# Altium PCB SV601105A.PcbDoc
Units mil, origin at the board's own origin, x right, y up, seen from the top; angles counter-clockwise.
Board outline 2000 x 2250 mil, 4 copper layers (Top Layer, GND_PLANE, POWER_PLANE, Bottom Layer), stack 90 mil thick; 33 components, 23 nets, 133 pads, 3 vias.
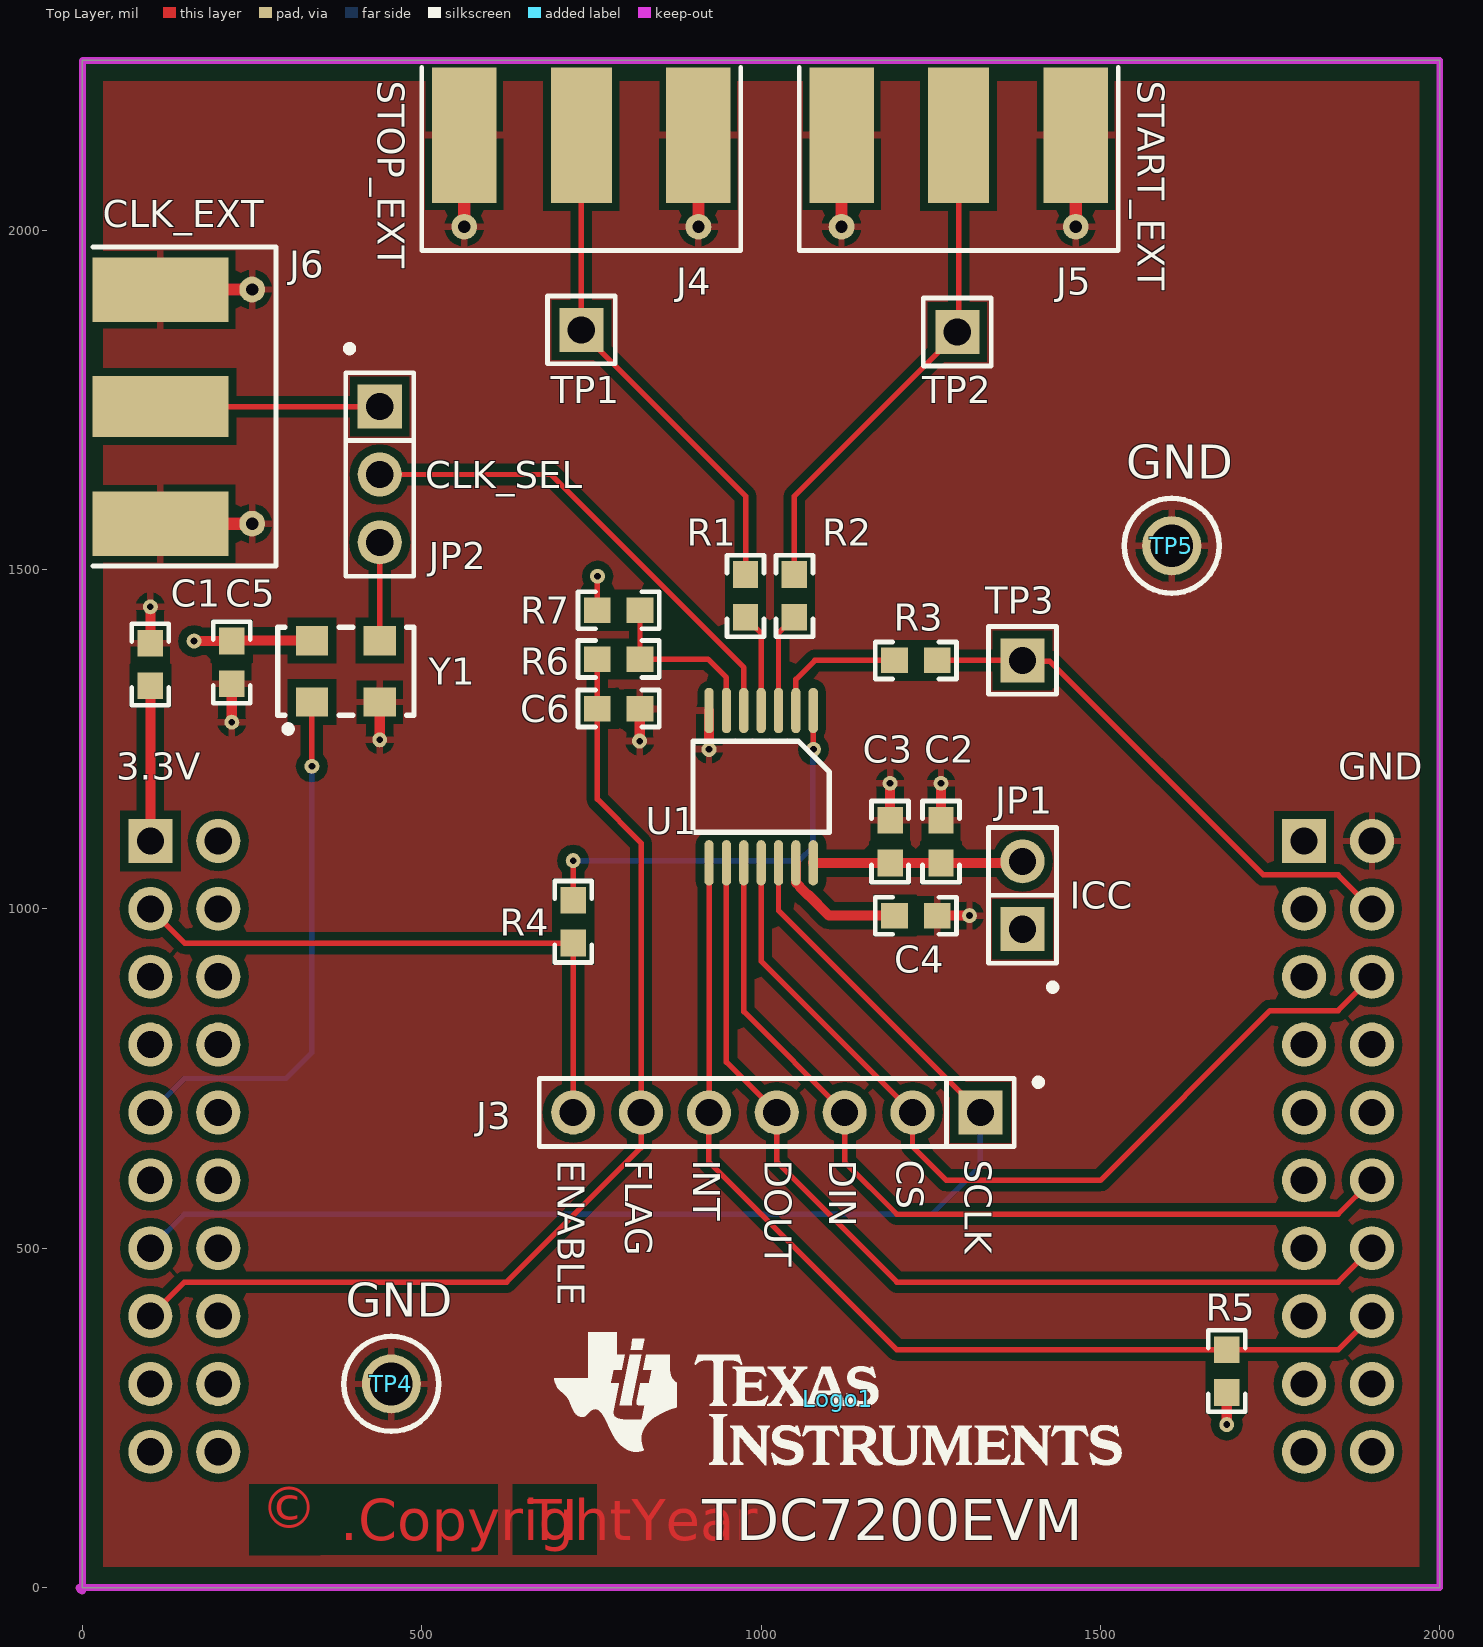
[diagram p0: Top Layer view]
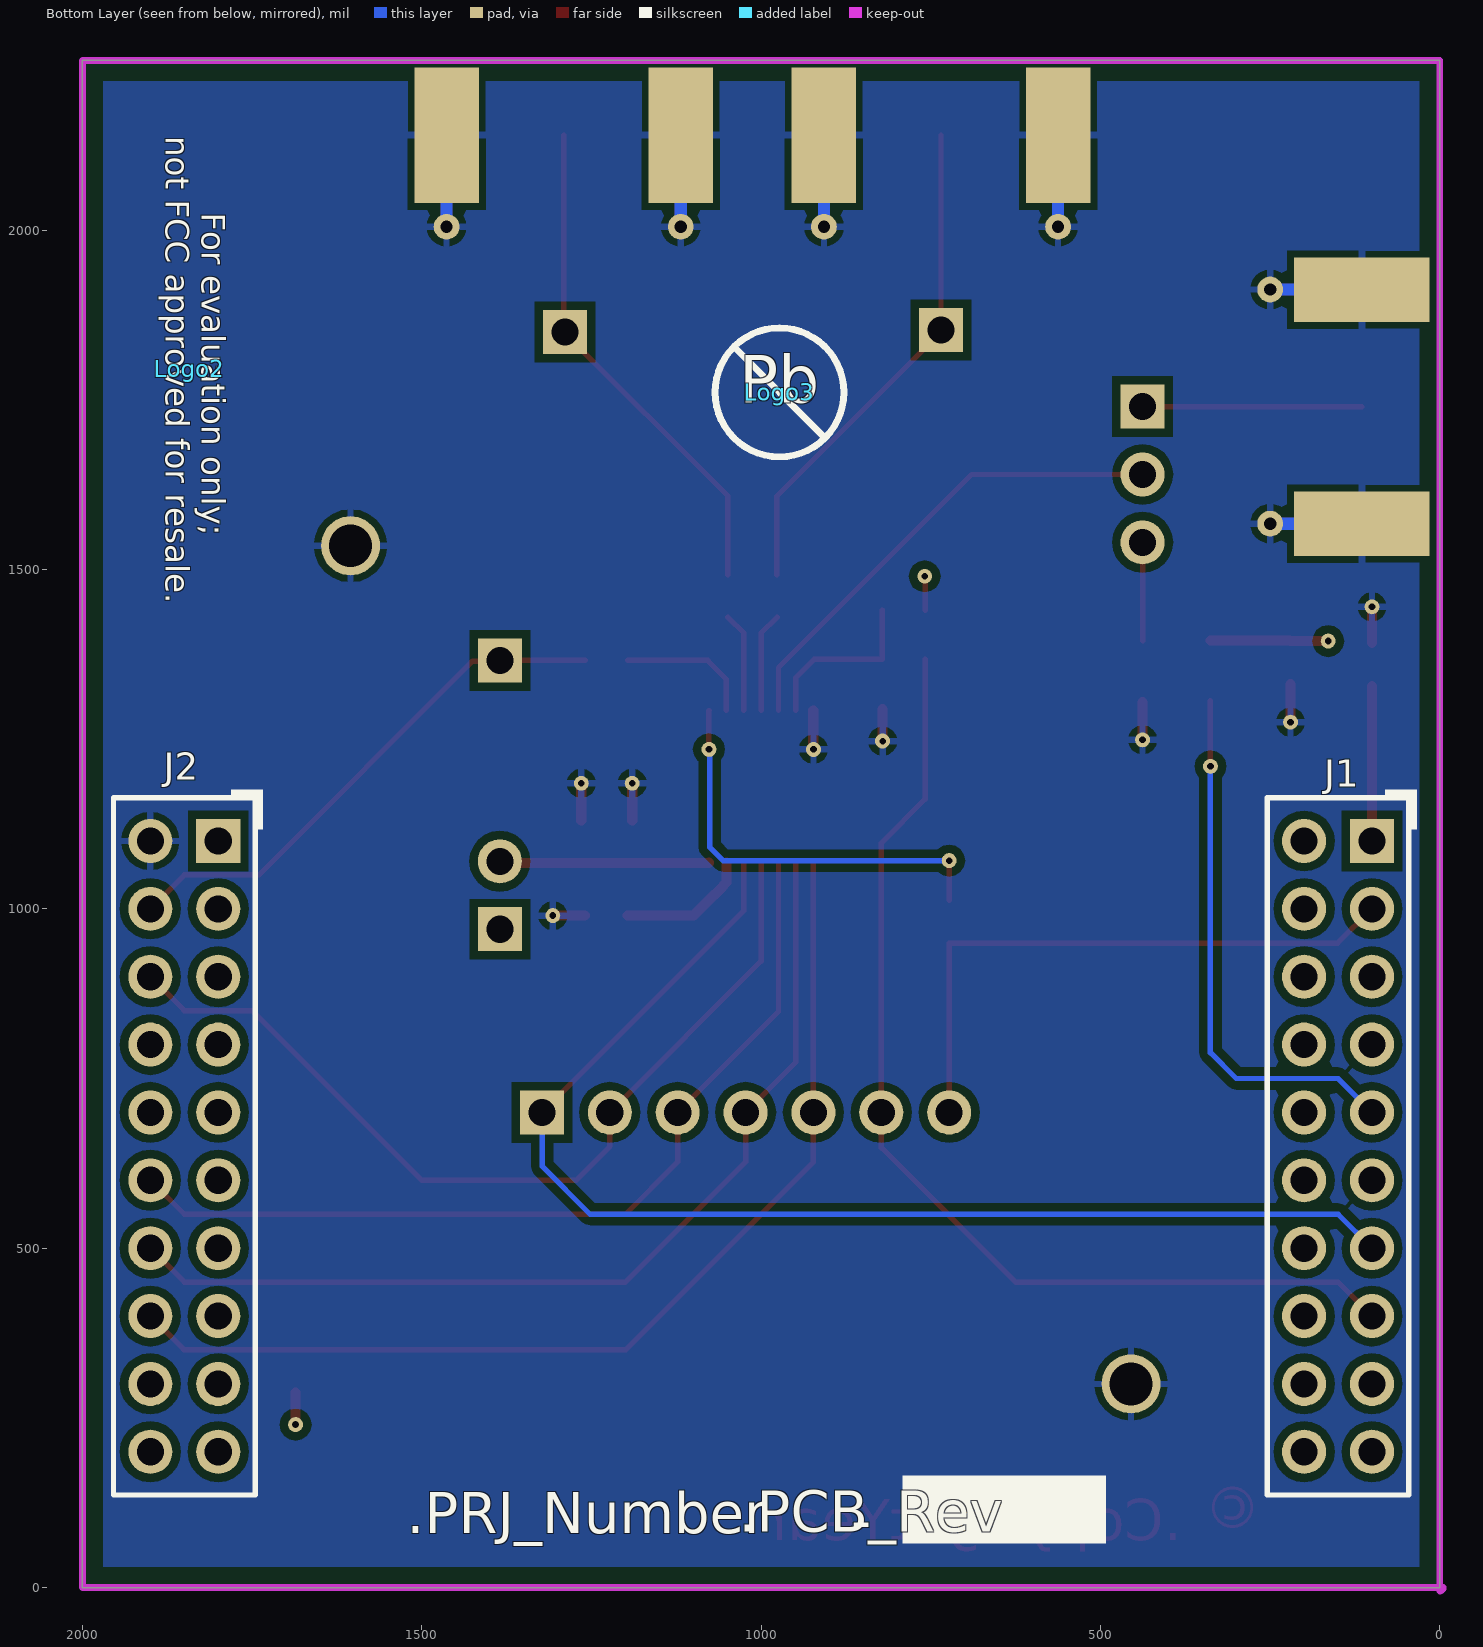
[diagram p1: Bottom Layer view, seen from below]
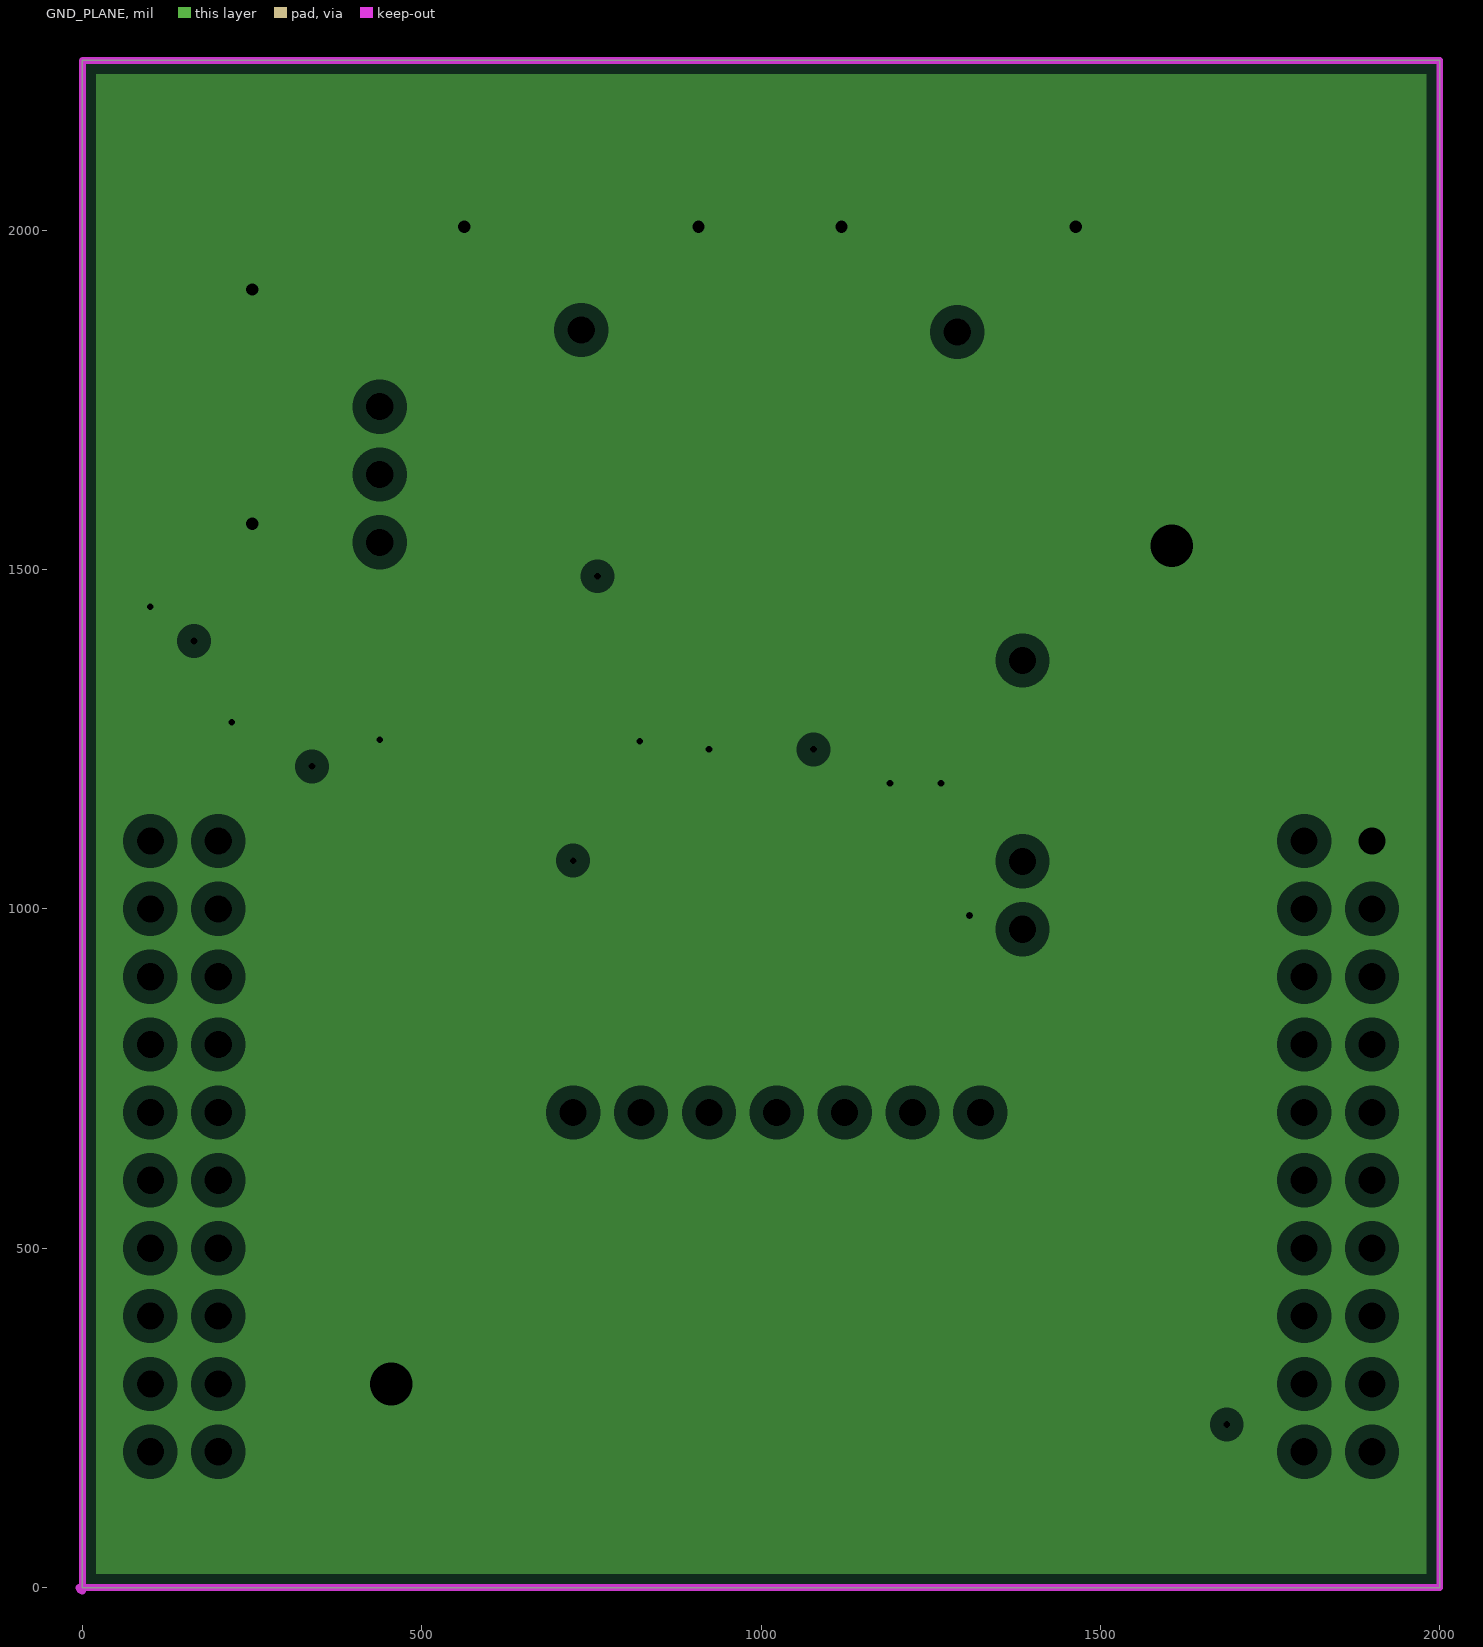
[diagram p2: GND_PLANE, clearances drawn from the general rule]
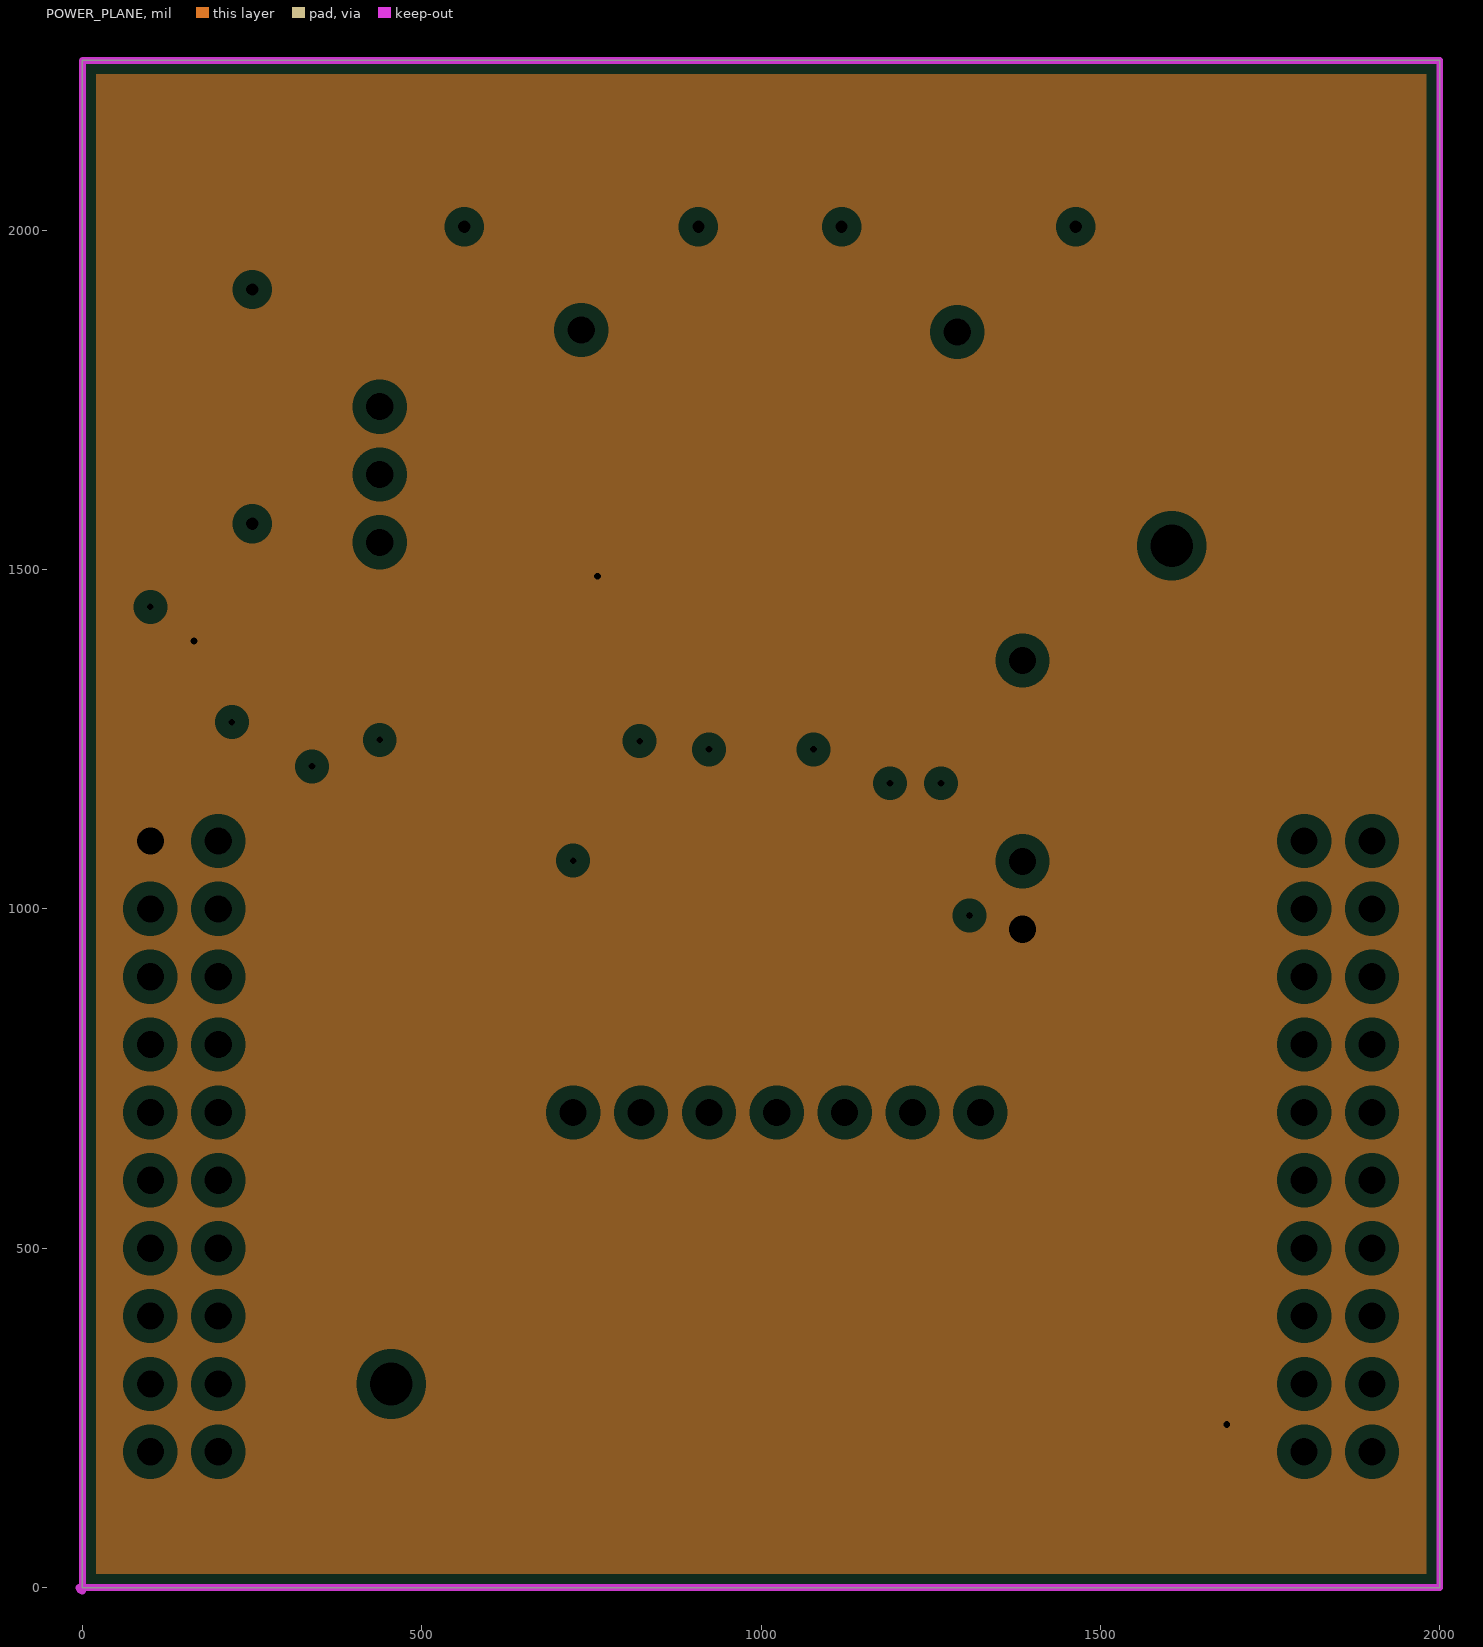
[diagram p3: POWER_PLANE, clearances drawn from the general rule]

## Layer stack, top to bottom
Top Layer: signal copper 1.4
Dielectric: core 59.2, FR-4, Dk 4.8
GND_PLANE: plane copper 1.4, net GND
Dielectric: prepreg 12.6, FR-4, Dk 4.8
POWER_PLANE: plane copper 1.4, net VCC
Dielectric: core 12.6, FR-4, Dk 4.8
Bottom Layer: signal copper 1.4

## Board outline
0,0 0,2250 2000,2250 2000,0

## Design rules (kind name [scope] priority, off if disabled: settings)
AcuteAngle [All] p1: minimum=4.50000000000000E+0001 checktracksonly=FALSE
AssemblyTestPointUsage [All] p1: valid=2
Clearance Clearance_BoardEdge_MountingHoles [OnCopper and InComponentClass('Mounting Holes') vs IsKeepOut] p1: gap=40
Clearance Clearance_BoardEdge_Poly [OnCopper and InPoly vs IsKeepOut] p2: gap=25
Clearance Clearance_BoardEdge [OnCopper and Not InComponentClass('Logo') and not InComponentClass('FiducialMark') and not InRegion(1000,500,4000,800) and Not IsKeepout vs IsKeepOut] p3: gap=5
Clearance Clearance_Poly [InPolygon] p4: gap=12
Clearance [All] p5: gap=6
ComponentClearance ComponentClearance_Logo [InComponentClass('Logo')] p1: gap=50 collisioncheckmode=3 verticalgap=10 showdistances=FALSE
ComponentClearance ComponentClearance_ScrewToNut [(HasFootprint('NY PMS 440 0025 PH')) vs (HasFootprint('Keystone_1902C'))] p2: gap=5 collisioncheckmode=3 verticalgap=10 showdistances=FALSE
ComponentClearance ComponentClearance_MountingHoles [InComponentClass('Mounting Holes')] p3: gap=250 collisioncheckmode=3 verticalgap=100000 showdistances=FALSE
ComponentClearance ComponentClearance_SmallPassives [HasFootprint('0201*') or HasFootprint('0402*') or HasFootprint('0508') or HasFootprint('0603*') or HasFootprint('0612') or HasFootprint('0805*') or HasFootprint('0815*') or HasFootprint('0830*') or HasFootprint('1206*') or HasFootprint('1210*') or HasFootprint('1808*') or HasFootprint('1812*') or HasFootprint('1825*') or HasFootprint('2010*') or HasFootprint('2220*') or HasFootprint('2225*') or HasFootprint('2512*') or HasFootprint('2728*') or HasFootprint('3518*') vs HasFootprint('0201*') or HasFootprint('0402*') or HasFootprint('0508') or HasFootprint('0603*') or HasFootprint('0612') or HasFootprint('0805*') or HasFootprint('0815*') or HasFootprint('0830*') or HasFootprint('1206*') or HasFootprint('1210*') or HasFootprint('1808*') or HasFootprint('1812*') or HasFootprint('1825*') or HasFootprint('2010*') or HasFootprint('2220*') or HasFootprint('2225*') or HasFootprint('2512*') or HasFootprint('2728*') or HasFootprint('3518*')] p4: gap=20 collisioncheckmode=3 verticalgap=10 showdistances=FALSE
ComponentClearance ComponentClearance_THtoSMT [IsThruComponent vs IsSMTComponent] p5: gap=20 collisioncheckmode=3 verticalgap=30 showdistances=FALSE
ComponentClearance ComponentClearance_THtoTH [IsThruComponent vs IsThruComponent] p6: gap=20 collisioncheckmode=3 verticalgap=30 showdistances=FALSE
ComponentClearance [All] p7: gap=40 collisioncheckmode=3 verticalgap=10 showdistances=FALSE
DiffPairsRouting [All] p1: maxlimit=100 minlimit=10 mostfreqgap=10 maxuncoupledlength=1000
FabricationTestPointUsage TestPointUsage [All] p1: valid=2 allowmultiple=FALSE
FabricationTestpoint Testpoint [All] p1: side=3 testpointundercomponent=TRUE minsize=40 maxsize=100 preferedsize=60 minholesize=0 maxholesize=40 preferedholesize=32 testpointgrid=1 allowsidetop=TRUE allowsidebottom=TRUE usegrid=TRUE gridtolerance=0.01
FanoutControl Fanout_LCC [IsLCC] p1: bgadir=Out bgaviamode=Centered fanoutstyle=Auto fanoutdirection=Alternating viagrid=1 // Fanout_LCC (Default Rule)
FanoutControl Fanout_BGA [IsBGA] p2: bgadir=Out bgaviamode=Centered fanoutstyle=Auto fanoutdirection=Alternating viagrid=1 // Fanout_BGA (Default Rule)
FanoutControl Fanout_Default [All] p4: bgadir=Out bgaviamode=Centered fanoutstyle=Auto fanoutdirection=Alternating viagrid=1 // Fanout_Default (Default Rule)
FanoutControl Fanout_Small [(CompPinCount < 5)] p5: bgadir=Out bgaviamode=Centered fanoutstyle=Auto fanoutdirection=OutThenIn viagrid=1 // Fanout_Small (Default Rule)
HoleSize [All] p1: absolutevalues=TRUE maxlimit=251 minlimit=8 maxpercent=80.000 minpercent=20.000
MinimumAnnularRing [All] p1: minimumring=5
MinimumSolderMaskSliver MinimumSolderMaskSliver_Logo [InComponentClass('Logo') vs InComponentClass('Logo')] p1: minsoldermaskwidth=0.7
MinimumSolderMaskSliver [All] p2: minsoldermaskwidth=4
PlaneClearance [All] p1: clearance=20
PlaneConnect [All] p1: planeconnectstyle=Relief reliefexpansion=10 reliefentries=4 reliefconductorwidth=10 reliefairgap=10
PolygonConnect [All] p1: connectstyle=Relief reliefconductorwidth=10 reliefentries=4 polygonreliefangle="90 Angle" airgapwidth=10
RoutingVias [All] p1: holewidth=16 width=34 viastyle="Through Hole" minholewidth=8 minwidth=20 maxholewidth=40 maxwidth=65
SMDToCorner [All] p1: distance=16000
SilkToSilkClearance [All] p1: silktosilkclearance=5
SilkscreenOverComponentPads [All] p1: minsilkscreentomaskgap=5
SolderMaskExpansion [All] p1: expansion=3
Width [All] p1: maxlimit=100 minlimit=6 preferedwidth=10 checkconnectedcopper=TRUE
13 further rules are at their usual default settings.

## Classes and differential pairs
component class AssemblyNote: ZZ1 ZZ2
component class Header: J3 JP1 JP2 TP1 TP2 TP3
component class Logo: Logo1

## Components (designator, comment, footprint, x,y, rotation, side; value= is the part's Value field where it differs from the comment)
C1 "C0603C106M9PACTU" 0603 100,1360 r90 top
C2 "0603YC104JAT2A" 0603 1265,1099 r90 top
C3 "06031C103JAT2A" 0603 1190,1099 r90 top
C4 "EMK107B7105KA-T" 0603 1228,990 r180 top
C5 "06031C103JAT2A" 0603 220,1363 r270 top
C6 "EMK107B7105KA-T" 0603 790,1295 r0 top
J1 "PPPC102LFBN-RC" Sullins_PPPC102LFBN-RC 150,650 r90 bottom
J2 "PPPC102LFBN-RC" Sullins_PPPC102LFBN-RC 1850,650 r90 bottom
J3 "TSW-107-07-G-S" TSW-107-07-G-S 1023,700 r180 top
J4 "STOP_EXT" JOHNSON_142-0701-801 735,2140 r0 top
J5 "START_EXT" JOHNSON_142-0701-801 1291,2140 r0 top
J6 "EXT_CLOCK" JOHNSON_142-0701-801 115,1740 r90 top
JP1 "ICC" TSW-102-07-G-S 1385,1020 r90 top
JP2 "CLK_SEL" TSW-103-07-G-S 438,1640 r270 top
Logo1 "Texas Instruments" TI_Stacked_Overlay_Small 1113.2,278.16 r0 top
Logo2 "FCC disclaimer" FCC_disclaimer_stacked 1843,1796.07 r270 bottom
Logo3 "Pb-Free Symbol" Pb-Free_Overlay_Medium 973,1761 r180 bottom
R1 "CRCW060349R9FKEA" 0603 977,1461 r90 top
R2 "CRCW060349R9FKEA" 0603 1049,1461 r90 top
R3 "CRCW06030000Z0EA" 0603 1228,1366 r0 top
R4 "CRCW06031K00FKEA" 0603 723,981 r90 top
R5 "CRCW060310K0FKEA" 0603 1686,319 r270 top
R6 "CRCW06030000Z0EA" 0603 790,1368 r0 top
R7 "CRCW060310K0FKEA" 0603 790,1440 r180 top
TP1 "TSW-101-07-G-S" TSW-101-07-G-S 735,1853 r0 top
TP2 "TSW-101-07-G-S" TSW-101-07-G-S 1289,1850 r0 top
TP3 "TSW-101-07-G-S" TSW-101-07-G-S 1385,1366 r0 top
TP4 "GND" Keystone5011 455,300 r0 top
TP5 "GND" Keystone5011 1605,1535 r0 top
U1 "TDC7200PW" PW0014A_N 1000,1180 r270 top
Y1 "ASFLMB-8.000MHZ-LY-T" Abracon_ASFLMB 388,1350 r90 top
ZZ1 "Short SH-JP1 on JP1 pin 1-2" AssemblyNote 185,3215 r0 top
ZZ2 "Short SH-JP2 on JP2 pins 2-3" AssemblyNote 185,3070 r0 top

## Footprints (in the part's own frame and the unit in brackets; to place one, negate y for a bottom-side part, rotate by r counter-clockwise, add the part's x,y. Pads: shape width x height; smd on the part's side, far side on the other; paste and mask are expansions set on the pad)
0603 [mm] "0603 from SM-752 data"
  rect 1x0.95 smd: 1(-0.8,0) 2(0.8,0)
  silkscreen extent -1.52,-0.69 1.52,0.69, body extent -0.87,-0.47 0.87,0.47, height 0.85
Abracon_ASFLMB [mm] "Abracon"
  rect 1.1x1.2 smd: 1(-1.15,1.27) 2(-1.15,-1.27) 3(1.15,-1.27) 4(1.15,1.27)
  silkscreen extent -2.29,-2.55 1.65,2.55, body extent -1.65,-2.55 1.65,2.55, height 0.9
AssemblyNote [mil] "Assembly Note"
FCC_disclaimer_stacked [mil]
JOHNSON_142-0701-801 [mil] "Johnson Components recommended land pattern"
  rect 90x200 smd: 1(0,0)
  round 38 hole 18: 2(-172.5,-135) 3(172.5,-135)
  rect 95x200 smd: 2(-172.5,0) 3(172.5,0)
  rect 95x200 smd far side: 4(-172.5,0) 5(172.5,0)
  Top Layer lines w18: -172.5,-135 -172.5,0 ; 172.5,-135 172.5,0
  Bottom Layer lines w18: -172.5,-135 -172.5,0 ; 172.5,-135 172.5,0
  silkscreen extent -235,-170 235,100, body extent -190,-92 190,480, height 165
Keystone5011 [mil] "Keystone Multipurpose loops"
  round 87 hole 63: 1(0,0)
  silkscreen extent -70,-70 70,70, body extent -63,-63 63,62, height 319
Pb-Free_Overlay_Medium [mil]
  silkscreen extent -95,-95 95,95
PW0014A_N [mm] "TSOP, 14-Leads, Body 5x4.4mm, Pitch 0.65mm, IPC Medium Density"
  oval 1.7x0.35 smd: 1(-2.85,1.95) 2(-2.85,1.3) 3(-2.85,0.65) 4(-2.85,0) 5(-2.85,-0.65) 6(-2.85,-1.3) 7(-2.85,-1.95) 8(2.85,-1.95) 9(2.85,-1.3) 10(2.85,-0.65) 11(2.85,0) 12(2.85,0.65) 13(2.85,1.3) 14(2.85,1.95)
  silkscreen extent -1.7,-2.55 1.7,2.55, body extent -3.21,-2.5 3.21,2.5, height 0.98
Sullins_PPPC102LFBN-RC [mil] "Sullins"
  rect 65x65 hole 40: 1(450,-50)
  round 65 hole 40: 2(450,50) 3(350,-50) 4(350,50) 5(250,-50) 6(250,50) 7(150,-50) 8(150,50) 9(50,-50) 10(50,50) 11(-50,-50) 12(-50,50) 13(-150,-50) 14(-150,50) 15(-250,-50) 16(-250,50) 17(-350,-50) 18(-350,50) 19(-450,-50) 20(-450,50)
  silkscreen extent -514,-116 526,104, body extent -514,-104 514,104, height 335
TI_Stacked_Overlay_Small [mil]
  silkscreen extent -418,-98 418,98
TSW-101-07-G-S [mm] "Samtec 100mil, 1pos, 230 mil above insulator"
  rect 1.65x1.65 hole 1.016 mask+0: 1(0,0)
  silkscreen extent -1.27,-1.27 1.27,1.27, body extent -1.27,-1.27 1.27,1.27, height 8.38
TSW-102-07-G-S [mm] "Samtec 100mil, 1x2, 230 mil above insulator"
  rect 1.65x1.65 hole 1.016 mask+0: 1(-1.27,0)
  round 1.65 hole 1.016 mask+0: 2(1.27,0)
  silkscreen extent -3.56,-1.27 2.54,1.27, body extent -2.54,-1.27 2.54,1.27, height 8.38
TSW-103-07-G-S [mm] "Samtec 100mil, 1x3, 230 mil above insulator"
  rect 1.65x1.65 hole 1.016: 1(-2.54,0)
  round 1.65 hole 1.016: 2(0,0) 3(2.54,0)
  silkscreen extent -4.83,-1.27 3.81,1.27, body extent -3.81,-1.27 3.81,1.27, height 8.38
TSW-107-07-G-S [mm] "Samtec 100mil, 1x7, 230 mil above insulator"
  rect 1.65x1.65 hole 1.016 mask+0: 1(-7.62,0)
  round 1.65 hole 1.016 mask+0: 2(-5.08,0) 3(-2.54,0) 4(0,0) 5(2.54,0) 6(5.08,0) 7(7.62,0)
  silkscreen extent -9.92,-1.27 8.89,1.27, body extent -8.89,-1.27 8.89,1.27, height 8.38

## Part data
C1: "CAP, CERM, 10uF, 6.3V, +/-20%, X5R, 0603"
C2: "CAP, CERM, 0.1uF, 16V, +/-5%, X7R, 0603"
C3 C5: "CAP, CERM, 0.01uF, 100V, +/-5%, X7R, 0603"
C4 C6: "CAP, CERM, 1uF, 16V, +/-10%, X7R, 0603"
J1 J2: "Receptacle, 10x2, 100mil, TH"
J3: "Header, TH, 100mil, 7x1, Gold plated, 230 mil above insulator"
J4 J5 J6: library part 142-0701-801, "Connector, End launch SMA, 50 ohm, SMT"
JP1: library part TSW-102-07-G-S, "Header, TH, 100mil, 2x1, Gold plated, 230 mil above insulator"
JP2: library part TSW-103-07-G-S, "Header, TH, 100mil, 3x1, Gold plated, 230 mil above insulator"
Logo1: library part TI_Logo, "Texas Instrument Corporate Signature"
Logo2: library part FCC_disclaimer, "FCC_disclaimer"
Logo3: library part Pb-Free
R1 R2: "RES, 49.9 ohm, 1%, 0.1W, 0603"
R3 R6: "RES, 0 ohm, 5%, 0.1W, 0603"
R4: "RES, 1.00k ohm, 1%, 0.1W, 0603"
R5 R7: "RES, 10.0k ohm, 1%, 0.1W, 0603"
TP1 TP2 TP3: "Header, TH, 100mil, 1pos, Gold plated, 230 mil above insulator"
TP4 TP5: library part 5011, "Test Point, Multipurpose, Black, TH"
U1: "STOPWATCH IC FOR TIME MEASUREMENT BETWEEN TWO EVENTS, PW0014A"
Y1: "OSC, 8MHz, 15pF, SMD"
ZZ1 ZZ2: library part AssemblyNote

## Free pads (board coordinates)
  round 22 hole 10: 0(100,1445) 0(164.5,1394.5) 0(220,1275) 0(338,1210) 0(438,1249) 0(723,1071) 0(1077,1235) 0(1190,1185) 0(1265,1185) 0(1307,990) 0(1686,240)

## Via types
v1: diameter 22, hole 10, Top Layer to Bottom Layer, 3 vias

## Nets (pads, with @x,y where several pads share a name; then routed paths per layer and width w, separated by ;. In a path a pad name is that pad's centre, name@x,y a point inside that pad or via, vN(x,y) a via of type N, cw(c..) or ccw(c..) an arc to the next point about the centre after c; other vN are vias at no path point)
CLOCK_TDC_CAL: JP2.2 U1.5 | length 717.6
  Top Layer w8: JP2.2 690,1640 974.41,1355.59 U1.5
CS: J2.6 J3.2 U1.11 | length 1332.1
  Top Layer w8: U1.11 1000,923 J3.2 1223,650 1273,600 1500,600 1750,850 1850,850 J2.6
DIN: J2.12 J3.3 U1.10 | length 1331.9
  Top Layer w8: U1.10 974.41,848.59 J3.3 1123,627 1200,550 1850,550 J2.12
DOUT: J2.14 J3.4 U1.9 | length 1442.5
  Top Layer w8: U1.9 948.82,774.18 J3.4 1023,627 1200,450 1850,450 J2.14
ENABLE: J1.3 J3.7 R4.1 | length 893.4
  Top Layer w8: J1.3 150.5,949.5 R4.1 J3.7
EXT_CLOCK: J6.1 JP2.1 | length 323
  Top Layer w8: J6.1 JP2.1
FLAG: C6.1 J1.15 J3.6 R6.1 | length 1582.4
  Top Layer w8: J1.15 150,450 625,450 823,648 J3.6 823,1097 758.5,1161.5 C6.1 R6.1
  Bottom Layer w8: J1.15@90,400 J1.15
GND: C1.2 C2.2 C3.2 C4.1 C5.2 C6.2 J2.2 J4.2 J4.3 J4.4 J4.5 J5.2 J5.3 J5.4 J5.5 J6.2 J6.3 J6.4 J6.5 pad.0@100,1445 pad.0@220,1275 pad.0@438,1249 pad.0@1190,1185 pad.0@1265,1185 pad.0@1307,990 TP4.1 TP5.1 U1.7 Y1.2 | length 427.7
  Top Layer w8: C6.2@821,1294.5 C6.2 ; v1(923,1235) v1@923.23,1235.23
  Top Layer w15: C1.2 pad.0@100,1445 ; pad.0@220,1275 C5.2 ; pad.0@438,1249 Y1.2 ; v1(821,1247) C6.2@821,1294.5 ; v1@923.23,1235.23 U1.7 ; C3.2 pad.0@1190,1185 ; C4.1 pad.0@1307,990 ; C2.2 pad.0@1265,1185
INT: J2.16 J3.5 R5.1 U1.8 | length 1552.9
  Top Layer w8: U1.8 923.23,700.23 J3.5 923,627 1199.5,350.5 1616,350.5 1850.5,350.5 J2.16
NetR3_1: R3.1 U1.2 | length 202.8
  Top Layer w8: U1.2 1051.18,1338.18 1079,1366 R3.1
NetR4_2: pad.0@723,1071 pad.0@1077,1235 R4.2 U1.1 | length 622.1
  Top Layer w8: R4.2 pad.0@723,1071 ; U1.1 1077,1291.98 pad.0@1077,1235
  Bottom Layer w8: pad.0@723,1071 1056,1071 1076,1091 pad.0@1076,1236
NetR6_2: R6.2 R7.1 U1.6 | length 259.2
  Top Layer w8: R7.1 R6.2 921.64,1368 948.82,1340.82 U1.6
OSC_ENABLE: J1.9 pad.0@338,1210 Y1.1 | length 793.1
  Top Layer w8: pad.0@338,1210 Y1.1@338,1306.69
  Bottom Layer w8: J1.9 150,750 300,750 338,788 pad.0@338,1210
OSC_OUT: JP2.3 Y1.3 | length 144.7
  Top Layer w8: Y1.3 JP2.3
SCLK: J1.13 J3.1 U1.12 | length 1853.1
  Top Layer w8: J1.13 J1.13@110,500 ; U1.12 1025.59,997.41 J3.1
  Bottom Layer w8: J1.13 150,550 1252,550 1322.5,620.5 1322.5,699.5 J3.1
START_EXT_IN: J5.1 R2.2 TP2.1 | length 747.7
  Top Layer w8: R2.2 1049,1608 1291,1850 J5.1
START_TDC: R2.1 U1.3 | length 147
  Top Layer w8: U1.3 1025.59,1406.09 R2.1
STOP_EXT_IN: J4.1 R1.2 TP1.1 | length 747.7
  Top Layer w8: J4.1 735,1850 977,1608 R1.2
STOP_TDC: R1.1 U1.4 | length 147
  Top Layer w8: R1.1@976.59,1429.5 1000,1406.09 U1.4
TRIG: J2.4 R3.2 TP3.1 | length 792.1
  Top Layer w8: R3.2 TP3.1 1386,1365 1425,1365 1740,1050 1850,1050 J2.4
VCC: C1.1 C5.1 J1.1 JP1.1 pad.0@164.5,1394.5 pad.0@1686,240 R5.2 R7.2 Y1.4 | length 498.9
  Top Layer w8: R7.2 758.5,1489.5 v1(759,1490)
  Top Layer w15: J1.1 C1.1 ; pad.0@164.5,1394.5 C5.1 ; C5.1@220.78,1395.28 Y1.4 ; pad.0@1686,240 R5.2
VDD: C2.1 C3.1 JP1.2 U1.14 | length 308.6
  Top Layer w15: U1.14 1077.06,1067.5 C3.1 C2.1 1384.5,1067.5 JP1.2@1385,1067
VREG: C4.2 U1.13 | length 195
  Top Layer w15: U1.13 1051.18,1038.82 1056.38,1033.62 1056.38,1032.77 1068.33,1020.83 1069.17,1020.83 1100,990 C4.2
pads on no net: J1.2 J1.4 J1.5 J1.6 J1.7 J1.8 J1.10 J1.11 J1.12 J1.14 J1.16 J1.17 J1.18 J1.19 J1.20 J2.1 J2.3 J2.5 J2.7 J2.8 J2.9 J2.10 J2.11 J2.13 J2.15 J2.17 J2.18 J2.19 J2.20

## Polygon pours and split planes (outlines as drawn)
GND on Top Layer "Top Layer-GND" (solid, pour order 2): 0,2250 0,0 2000,0 2000,2250
GND on Bottom Layer "Bottom Layer-GND" (solid, pour order 4): 0,2250 0,0 2000,0 2000,2250
GND on GND_PLANE (split plane): 1979.9,20.1 20.1,20.1 20.1,2229.9 1979.9,2229.9
VCC on POWER_PLANE (split plane): 1979.9,20.1 20.1,20.1 20.1,2229.9 1979.9,2229.9

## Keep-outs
Keep-Out Layer:
  lines w10: -5,0 ccw(c0,0) 0,-5 ; -5,0 ccw(c0,0) 0,-5 ; -5,0 ccw(c0,0) 0,-5 ; -5,0 ccw(c0,0) 0,-5 ; -5,0 ccw(c0,0) 0,-5 ; -5,0 ccw(c0,0) 0,-5 ; 4950,-5 ccw(c4950,0) 4955,0 ; 4950,-5 ccw(c4950,0) 4955,0 ; 4950,-5 ccw(c4950,0) 4955,0 ; 4950,-5 ccw(c4950,0) 4955,0 ; 4950,-5 ccw(c4950,0) 4955,0 ; 4950,-5 ccw(c4950,0) 4955,0 ; 0,0 0,2250 2000,2250 2000,0 0,0
  text ".Layer_Name" at 577,-858.49 h60

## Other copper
Top Layer:
  text ".CopyrightYear" at 380,70 h60
  text "TI" at 656,70 h60
  text "©" at 263,66.48 h105
  text ".Layer_Name" at 577,-858.49 h60
Bottom Layer:
  text ".Layer_Name" at 577,-858.49 h60

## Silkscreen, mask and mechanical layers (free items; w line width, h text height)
Top Overlay:
  text "START_EXT" at 1555,2220 h40 r270
  text "CLK_EXT" at 30,2004 h40
  text "CLK_SEL" at 505,1620 h40
  text "3.3V" at 50,1190 h40
  text "GND" at 1850,1190 h40
  text "ENABLE" at 700,630 h40 r270
  text "FLAG" at 800,630 h40 r270
  text "INT" at 900,630 h40 r270
  text "DOUT" at 1005,630 h40 r270
  text "DIN" at 1100,630 h40 r270
  text "CS" at 1200,630 h40 r270
  text "SCLK" at 1300,630 h40 r270
  text "TDC7200EVM" at 913.2,70 h60
  text ".Layer_Name" at 577,-858.49 h60
Bottom Overlay:
  rectangle: 492,65 792,165
  text ".PCB_Rev" at 1033,82 h60
  text ".PRJ_Number" at 1522,80 h60
  text "-" at 867,70 h60
  text ".Layer_Name" at 577,-858.49 h60
Top Paste:
  text ".Layer_Name" at 577,-858.49 h60
Bottom Paste:
  text ".Layer_Name" at 577,-858.49 h60
Top Solder:
  text ".Layer_Name" at 577,-858.49 h60
  text ".Layer_Name" at 577,-858.49 h60
Bottom Solder:
  text ".Layer_Name" at 577,-858.49 h60
Drill Guide:
  text ".Layer_Name" at 577,-858.49 h60
M1 Board Outline:
  the board outline again, w10
  text ".Layer_Name" at 577,-858.49 h60
M2 Board Dimensions:
  rectangle: -0.5,-285.5 124.5,-160.5
  rectangle: 124.5,-410.5 499.5,-285.5
  lines w7: -0.5,-285.5 999.5,-285.5 ; 124.5,-410.5 124.5,-160.5 ; 249.5,-410.5 249.5,-160.5 ; 499.5,-410.5 499.5,-160.5 ; 749.5,-410.5 749.5,-160.5 ; -0.5,-410.5 999.5,-410.5 999.5,-160.5 -0.5,-160.5 -0.5,-410.5
  lines w10: -0.5,-475.5 -0.5,-455.5 ; 59.5,-485.5 -0.5,-465.5 ; 59.5,-445.5 -0.5,-465.5 ; 223.58,-465.5 -0.5,-465.5 ; 775.42,-465.5 999.5,-465.5 ; 939.5,-485.5 999.5,-465.5 ; 939.5,-445.5 999.5,-465.5 ; 999.5,-475.5 999.5,-455.5
  text "1000 (mil)" at 233.58,-501.49 h60
  text ".Layer_Name" at 577,-858.49 h60
M3 3D STEP Top:
  text ".Layer_Name" at 577,-858.49 h60
M4 3D STEP Bottom:
  text ".Layer_Name" at 577,-858.49 h60
M5 Assembly Top:
  lines w7: 5139,110.5 6264,110.5 ; 5139,233 6261.5,233 ; 5454,-9.5 5454,353 ; 5839,-9.5 5139,-9.5 ; 5839,353 5139,353 ; 5139,-9.5 6264,-9.5 6264,353 5139,353 ; 5139,-9.5 5139,353
  lines w10: -292,-930.17 6308,-930.17 ; -292,-726.83 6310,-726.83 ; -292,-523.5 -292,-1133.5 3713,-1133.5 6310,-1133.5 6310,-523.5 -291.5,-523.5 -291.5,-1133.5 1284,-1133.5 ; 2173,-1133.5 2173,-523.5 ; 3440,-726.83 3440,-523.5 ; 4280,-726.83 4280,-523.5 ; 4902,-1140 4902,-937.17
  text "TABLE 1" at 5526.5,388 h40
  text "Variant" at 5164,278 h40
  text "Label text" at 5599,278 h40
  text "001" at 5231.5,158 h40
  text "TDC7200EVM" at 5509,155.5 h40
  text "COMPONENTS MARKED 'DNP' SHOULD NOT BE POPULATED." at 1153.5,-318.5 h60
  text "ASSEMBLY VARIANT:" at 1153,-434 h60
  text ".VariantName" at 2189,-434 h60
  text "PCB VIEWED FROM TOP SIDE" at -228.5,-655.67 h60
  text "BOARD #:" at 2248,-655.67 h60
  text ".PRJ_Number" at 2793.5,-655.67 h60
  text "REV:" at 3638,-655.67 h60
  text ".PCB_Rev" at 3929.5,-655.67 h60
  text "SVN REV:" at 4476,-655.67 h60
  text ".VersionControl_RevNumber" at 4982,-655.67 h60
  text "IGNORE ->" at -228.5,-858.49 h60
  text "PLOT NAME =" at -228.5,-1064.34 h60
  text ".plot_File_Name" at 577,-1064.34 h60
  text "GENERATED    :" at 2250,-1064.34 h60
  text ".Print_Date" at 3119.5,-1064.34 h60
  text ".Print_Time" at 3848.5,-1064.34 h60
  text "TEXAS INSTRUMENTS" at 5113,-1064.34 h60
M6 Assembly Bottom:
  lines w10: -292.5,-727.33 6309.5,-727.33 ; -290.5,-930.67 6309.5,-930.67 ; 1115.5,-1140.5 1115.5,-937.67 ; 1737.5,-727.33 1737.5,-524 ; 2577.5,-727.33 2577.5,-524 ; 3844.5,-1134 3844.5,-524 ; 4733.5,-1134 6309,-1134 6309,-524 -292.5,-524 -292.5,-1134 2304.5,-1134 6309.5,-1134 6309.5,-524
  text "COMPONENTS MARKED 'DNP' SHOULD NOT BE POPULATED." at 6102,-318 h60
  text ".VariantName" at 5058,-434 h60
  text "ASSEMBLY VARIANT:" at 6097,-434 h60
  text ".VersionControl_RevNumber" at 1035.5,-656.17 h60
  text "SVN REV:" at 1541.5,-656.17 h60
  text ".PCB_Rev" at 2088,-656.17 h60
  text "REV:" at 2379.5,-656.17 h60
  text ".PRJ_Number" at 3224,-656.17 h60
  text "BOARD #:" at 3769.5,-656.17 h60
  text "PCB VIEWED FROM BOTTOM SIDE" at 6246,-656.17 h60
  text "IGNORE ->" at 2547.85,-858.49 h60
  text "TEXAS INSTRUMENTS" at 904.5,-1064.84 h60
  text ".Print_Time" at 2169,-1064.84 h60
  text ".Print_Date" at 2898,-1064.84 h60
  text "GENERATED    :" at 3767.5,-1064.84 h60
  text ".plot_File_Name" at 5440.5,-1064.84 h60
  text "PLOT NAME =" at 6246,-1064.84 h60
M9 Title Sheet:
  drawing of 57 lines, arcs and shapes, not listed
  text "1" at 739.84,8036.5 h70
  text "2" at 3235.5,8036.5 h70
  text "3" at 5724.84,8036.5 h70
  text "4" at 8231.51,8036.5 h70
  text "5" at 10730.5,8036.5 h70
  text "6" at 13235.5,8036.5 h70
  text "A" at -416.5,6893.5 h70
  text "A" at 14383.5,6893.5 h70
  text "B" at -416.5,4513.5 h70
  text "B" at 14383.5,4513.5 h70
  text "C" at -416.5,2138.5 h70
  text "C" at 14383.5,2138.5 h70
  text "PROJECT TITLE:" at 11343.5,277.5 h45
  text ".PRJ_Title" at 11393.5,144.17 h70
  text "DESIGNED FOR:" at 11343.5,-23.5 h45
  text ".PRJ_Customer" at 11393.5,-163.5 h70
  text "D" at -416.5,-231.5 h70
  text "D" at 14383.5,-231.5 h70
  text "FILE NAME:" at 11343.5,-323.5 h45
  text ".PCB_File_Name_No_Path" at 11393.5,-443.5 h70
  text "Texas Instruments (TI) and/or its licensors do not warrant the accuracy or completeness of this specification" at 6374,-605.34 h45
  text "ENGINEER:" at 11343.5,-613.5 h45
  text "LAYOUT BY:" at 12848.5,-613.5 h45
  text "or any information contained therein. TI and/or its licensors do not warrant that this design will meet" at 6329.01,-718 h45
  text ".PRJ_Engineer" at 11393.5,-768.49 h70
  text ".PCB_Layout" at 12899,-768.49 h70
  text "the specifications, will be suitable for your application or fit for any particular purpose, or will operate in" at 6329.01,-830.67 h45
  text ".Layer_Name" at 577,-858.49 h60
  text "ALTIUM DESIGNER VERSION:" at 12848.5,-923.5 h45
  text "an implementation. TI and/or its licensors do not warrant that the design is production worthy. You should" at 6329.01,-943.33 h45
  text "completely validate and test your design implementation to confirm the system functionality for your application." at 6374,-1056 h45
  text ".print_Scale" at 11393.5,-1056.83 h70
  text ".Application_BuildNumber" at 12899,-1056.83 h70
  text "1" at 739.84,-1263.5 h70
  text "2" at 3235.5,-1263.5 h70
  text "3" at 5724.84,-1263.5 h70
  text "4" at 8231.51,-1263.5 h70
  text "5" at 10730.5,-1263.5 h70
  text "6" at 13235.5,-1263.5 h70
M10 Fab Notes:
  drawing of 212 lines, arcs and shapes, not listed
  text "DESIGN INFORMATION" at 12381.02,6810 h60
  text "(REFER ALSO ARRAY/PANEL PROFILING INFORMATION)" at 12019.46,6648.29 h60
  text "BOARD SIZE" at 11333.46,6644 h60
  text "2250MIL" at 11795.78,6516.18 h60
  text "X" at 12301.46,6516.18 h60
  text "2000MIL" at 12532.78,6516.18 h60
  text "Number of Layers :" at 11736.46,6319 h60
  text "4" at 12831.27,6309 h60
  text "MIN. TRACK WIDTH:" at 11736.46,6180 h60
  text "8" at 12832.7,6180 h60
  text "MIL" at 12987.46,6180 h60
  text "MIN. CLEARANCE:" at 11736.46,6048 h60
  text "8" at 12832.7,6048 h60
  text "MIL" at 12987.46,6048 h60
  text "MIN. VIA PAD SIZE:" at 11736.46,5916 h60
  text "24" at 12802.71,5916 h60
  text "MIL" at 12987.46,5916 h60
  text "0.05mm (2MIL)" at 12431.46,5774.29 h60
  text "MINIMUM ANNULAR RING" at 11407.23,5770 h60
  text "EXTERNAL" at 13139.46,5770 h60
  text "PER" at 11607.23,5652 h60
  text "IPC-D-275 CLASS 2 LEVEL C" at 11827.23,5652 h60
  text "MIL, HOLES" at 13315.46,5539.71 h60
  text "+/-" at 12923,5539 h60
  text "+/-" at 13777,5539 h60
  text "REGISTRATION TOLERANCES:" at 11407.23,5534 h60
  text "METAL" at 12607,5534 h60
  text "5" at 13183.2,5534 h60
  text "3" at 14016.2,5534 h60
  text "MIL" at 14132.46,5534 h60
  text "MATERIAL:" at 11332.46,5324.54 h60
  text "FR-4 High Tg" at 12318.9,5184.21 h60
  text "FR-408" at 11753.46,5175.64 h60
  text "X" at 12165.46,5175.64 h60
  text "OTHER" at 13241.46,5175.64 h60
  text "62 MIL (1.6mm) +/-10%" at 12073.56,5012.92 h60
  text "THICKNESS:" at 11407.23,5008.64 h60
  text "X" at 11945.4,5008.64 h60
  text "OTHER" at 13358.46,5008.64 h60
  text "TOLERANCE:" at 11407.23,4850.64 h60
  text "X" at 12246.53,4850.64 h60
  text "ANSI IPC-6012 TYPE 3 CLASS 2" at 12433.48,4850.64 h60
  text "OTHER +/-" at 12433.46,4694.64 h60
  text "BOW & TWIST:" at 11407.23,4537.64 h60
  text "X" at 12246.53,4537.64 h60
  text "ANSI IPC-6012 TYPE 3 CLASS 2" at 12433.48,4537.64 h60
  text "OTHER +/-" at 12433.46,4379.13 h60
  text "COPPER THICKNESS (FINISHED):" at 11332.46,4243.64 h60
  text "1.4MIL (1oz)" at 12212.46,4090.92 h60
  text "2MIL (1.4oz)" at 12979.46,4090.92 h60
  text "2.8MIL (2oz)" at 13706.46,4090.92 h60
  text "OUTER:" at 11689.46,4086.64 h60
  text "X" at 12084,4086 h60
  text "1.4MIL (1oz)" at 12212.46,3933.92 h60
  text "2.8MIL (2oz)" at 12979.46,3933.92 h60
  text "N/A" at 13706,3934.29 h60
  text "INNER SIGNAL:" at 11400.38,3929.64 h60
  text "X" at 12085.42,3929.64 h60
  text "DRILLING:" at 11332.46,3790.64 h60
  text "REFERENCE:" at 11407.23,3673.64 h60
  text "X" at 12055.46,3673.64 h60
  text "AS SHOWN" at 12242.46,3673.64 h60
  text "X" at 12956.46,3673.64 h60
  text "NC_DRILL FILES" at 13093.46,3673.64 h60
  text "PTH MIN COPPER THICKNESS:" at 11407.23,3515.64 h60
  text "X" at 12757.46,3515.64 h60
  text "1MIL" at 12894.46,3515.64 h60
  text "OTHER" at 13391.46,3515.64 h60
  text "BOARD FINISH:" at 11332.46,3356.64 h60
  text "SILKSCREEN:" at 11487.68,3238.64 h60
  text "X" at 12436.46,3238.64 h60
  text "TOP" at 12562.46,3238.64 h60
  text "X" at 12946.46,3238.64 h60
  text "BOTTOM" at 13073.46,3238.64 h60
  text "SILKSCREEN COLOR:" at 11487.68,3071.64 h60
  text "X" at 12435.42,3071.64 h60
  text "WHITE" at 12562.46,3071.64 h60
  text "OTHER" at 13073.46,3071.64 h60
  text "SOLDER RESIST COLOR:" at 11487.68,2901.64 h60
  text "X" at 12055.42,2742.44 h60
  text "GREEN" at 12182.46,2742.44 h60
  text "BLUE" at 12773.46,2742.44 h60
  text "OTHER" at 13311.46,2742.44 h60
  text "IMMERSION GOLD (ENIG)" at 12393.46,2553.92 h60
  text "ENEPIG" at 13731,2550.64 h60
  text "SURFACE FINISH:" at 11332.46,2549.64 h60
  text "X" at 12206.51,2549.64 h60
  text "IMM. TIN/SILVER OR EQUIV" at 11662,2392.64 h60
  text "OTHER" at 13093.46,2392.64 h60
  text "ARRAY/PANEL:" at 11332.46,2213.64 h60
  text "CUT AND TRIM PER MECH LAYER 1" at 12393.46,2209.35 h60
  text "N.C. ROUTE" at 12393.46,2057.64 h60
  text "V. SCORE" at 13259.46,2057.64 h60
  text "CERTIFICATION:" at 11332.46,1920.64 h60
  text "MATERIALS AND WORKMANSHIP FOR ALL PCBS" at 12057.46,1920.64 h60
  text "TO MEET OR EXCEED THE REQUIREMENTS OF:" at 12057.46,1822.64 h60
  text "X" at 11683.96,1686.13 h60
  text "ANSI IPC-A-600F CLASS ->" at 11822.96,1686.13 h60
  text "X" at 13462.02,1686.13 h60
  text "2" at 13580.96,1686.14 h60
  text "1" at 13265.96,1684.64 h60
  text "3" at 13934.96,1684.64 h60
  text "X" at 11686.02,1526.64 h60
  text "UL 94V-0" at 11822.96,1526.64 h60
  text "X" at 12498.02,1526.64 h60
  text "RoHS" at 12634.96,1526.64 h60
  text "OTHER" at 13279.36,1526.64 h60
  text "PER ORDER" at 13676.42,1526.64 h60
  text "ADDITIONAL REQUIREMENTS:" at 11332.46,1385.64 h60
  text "MICROSECTION:" at 11407.23,1270.64 h60
  text "YES" at 12312.96,1270.64 h60
  text "REQUIRED" at 13174.46,1114.49 h60
  text "BARE BOARD ELEC. TEST:" at 11407.23,1111.64 h60
  text "NONE" at 12712.96,1111.64 h60
  text "X" at 13047.46,1111.64 h60
  text "PER ORDER" at 13766.46,1111.64 h60
  text "MANUFACTURER'S UL:" at 11407.23,954.64 h60
  text "RAIL" at 12572.96,950.35 h60
  text "METAL" at 13064.77,950.35 h60
  text "X" at 13440,950 h60
  text "SILK" at 13576.46,950.35 h60
  text ".Layer_Name" at 577,-858.49 h60
M11 Gerber Information:
  lines w10: -292,-930.17 6308,-930.17 ; -292,-726.83 6310,-726.83 ; -292,-523.5 -292,-1133.5 3713,-1133.5 6310,-1133.5 6310,-523.5 -291.5,-523.5 -291.5,-1133.5 1284,-1133.5 ; 2173,-1133.5 2173,-523.5 ; 3440,-726.83 3440,-523.5 ; 4280,-726.83 4280,-523.5 ; 4902,-1140 4902,-937.17
  text "ALL ARTWORK VIEWED FROM TOP SIDE" at -228.5,-655.67 h60
  text "BOARD #:" at 2248,-655.67 h60
  text ".PRJ_Number" at 2793.5,-655.67 h60
  text "REV:" at 3638,-655.67 h60
  text ".PCB_Rev" at 3929.5,-655.67 h60
  text "SVN REV:" at 4476,-655.67 h60
  text ".VersionControl_RevNumber" at 4982,-655.67 h60
  text "LAYER NAME =" at -228.5,-858.49 h60
  text "PLOT NAME =" at -228.5,-1064.34 h60
  text ".plot_File_Name" at 577,-1064.34 h60
  text "GENERATED    :" at 2250,-1064.34 h60
  text ".Print_Date" at 3119.5,-1064.34 h60
  text ".Print_Time" at 3848.5,-1064.34 h60
  text "TEXAS INSTRUMENTS" at 5113,-1064.34 h60
M12 Stackup:
  lines w6: 11365,7691.75 14235,7691.75 ; 11365,7804.35 14235,7804.35 ; 11305,6986 ccw(c11341,6986) 11341,6950 14259,6950 ccw(c14259,6986) 14295,6986 14295,7899 ccw(c14259,7899) 14259,7935 11341,7935 ccw(c11341,7899) 11305,7899 11305,6986
  text "Layer Stack Up Detail for: SV601105A.PcbDoc" at 11365,7832.67 h50
  text "Layer" at 11365,7762.35 h26
  text "Gerber" at 12369.47,7762.35 h26
  text "Copper" at 13028.18,7762.35 h26
  text "Dielectric" at 13729.35,7762.35 h26
  text "Name" at 11365,7710.35 h26
  text "Document" at 12369.47,7710.35 h26
  text "Thickness" at 13028.18,7710.35 h26
  text "Material" at 13729.35,7710.35 h26
  text "Top Solder Mask" at 11365,7637.45 h36
  text "(.GTS)" at 12369.47,7637.45 h36
  text "Solder Resist" at 13729.35,7637.45 h36
  text "Top Layer" at 11365,7534.84 h36
  text "(.GTL)" at 12369.47,7534.84 h36
  text "1.4mil" at 13028.18,7534.84 h36
  text "FR-4" at 13729.35,7483.54 h36
  text "GND_PLANE" at 11365,7432.24 h36
  text "(.GP1)" at 12369.47,7432.24 h36
  text "1.4mil" at 13028.18,7432.24 h36
  text "FR-4" at 13729.35,7380.94 h36
  text "POWER_PLANE" at 11365,7329.64 h36
  text "(.GP2)" at 12369.47,7329.64 h36
  text "1.4mil" at 13028.18,7329.64 h36
  text "FR-4" at 13729.35,7278.33 h36
  text "Bottom Layer" at 11365,7227.03 h36
  text "(.GBL)" at 12369.47,7227.03 h36
  text "1.4mil" at 13028.18,7227.03 h36
  text "Bottom Solder Mask" at 11365,7124.43 h36
  text "(.GBS)" at 12369.47,7124.43 h36
  text "Solder Resist" at 13729.35,7124.43 h36
  text ".Layer_Name" at 577,-858.49 h60
M13 Component Bodies Top:
  text ".Layer_Name" at 577,-858.49 h60
M14 Component Bodies Bottom:
  text ".Layer_Name" at 577,-858.49 h60
M15 Courtyards Top:
  text ".Layer_Name" at 577,-858.49 h60
M16 Courtyards Bottom:
  text ".Layer_Name" at 577,-858.49 h60
Drill Drawing:
  lines w1: 2000,2250 2000.03,2250 ; 0,0 0.03,0 ; 0,0 0.03,0 ; 0,0 0.03,0 ; 0,2250 0.03,2250 0,2250 ; 100,200 100.03,200 100,200
  text ".legend" at 5122.5,725.5 h60
  text "Drill Table" at 5147.5,540.5 h60
  text ".Layer_Name" at 577,-858.49 h60

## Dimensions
0,0 to 0,2250 on M2 Board Dimensions
0,0 to 2000,0 on M2 Board Dimensions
